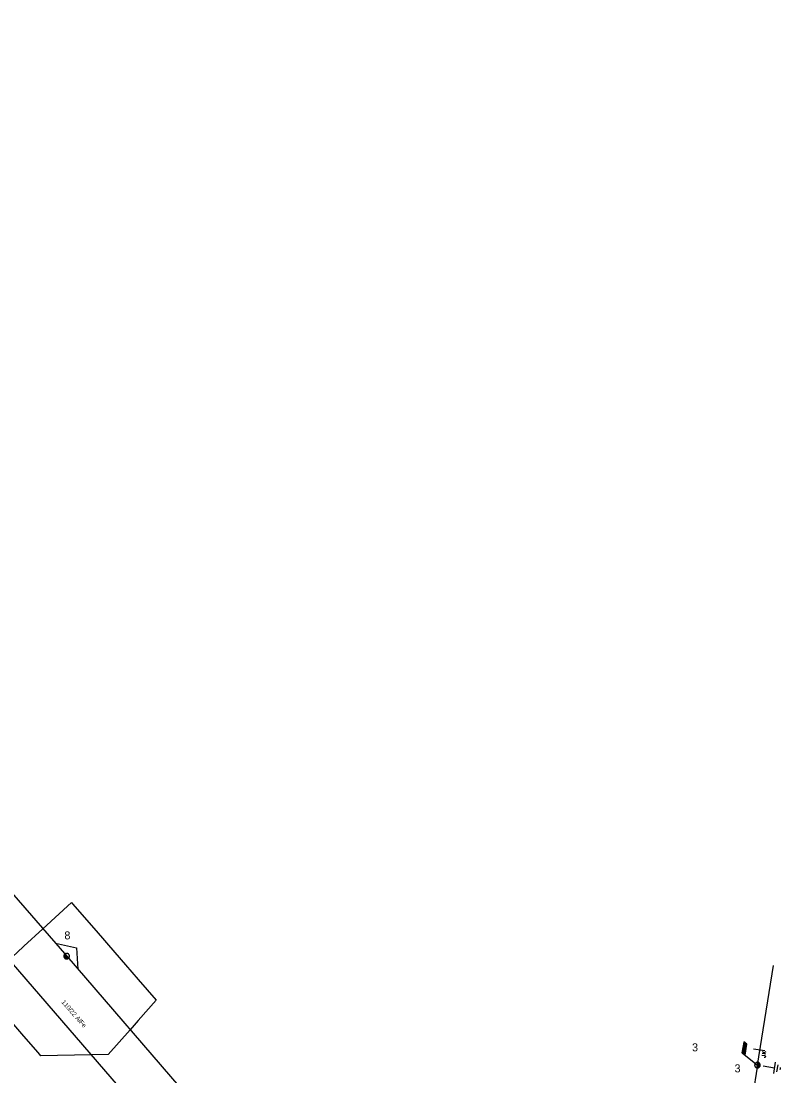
# Model space of a CAD drawing. Extents: x -540879 to -537255, y -1184046 to -1180016.
# Drawn here: x -537563.1 to -537397, y -1180339.5 to -1180108.9 of the extents above; entities that cross this region are included whole.
import ezdxf

# ---------------------------------------------------------------- set-up
doc = ezdxf.new("R2010")
doc.units = 0
for name, color, linetype in [('Default', 7, 'Continuous'), ('Vrstva 1', 7, 'Continuous'), ('Vrstva 11', 7, 'Continuous'), ('Vrstva 12', 7, 'Continuous'), ('Vrstva 13', 7, 'Continuous'), ('Vrstva 14', 7, 'Continuous'), ('Vrstva 15', 7, 'Continuous'), ('Vrstva 18', 7, 'Continuous'), ('Vrstva 2', 7, 'Continuous'), ('Vrstva 35', 7, 'Continuous')]:
    doc.layers.add(name, color=color, linetype=linetype)

# ---------------------------------------------------------------- blocks, each defined once
blk = doc.blocks.new('VN840')
at = {"layer": 'Vrstva 15'}
for points in [[(-0.01, 1.41), (-0.01, -1.09)], [(-1.51, -1.24), (-1.51, -1.15)], [(-1.48, -1.35), (-1.51, -1.24)], [(-1.33, -1.42), (-1.48, -1.35)], [(-1.27, -1.42), (-1.33, -1.42)], [(-1.13, -1.35), (-1.27, -1.42)], [(-1.09, -1.24), (-1.13, -1.35)], [(-1.09, -0.59), (-1.09, -1.24)], [(-0.68, -0.59), (-0.68, -1.42)], [(-0.68, -1.11), (-0.27, -0.59)], [(-0.54, -0.94), (-0.2, -1.42)]]:
    blk.add_lwpolyline(points, dxfattribs=at)
blk = doc.blocks.new('VN860')
at = {"layer": 'Vrstva 15'}
for points in [[(-3.74, 0), (0.01, 2.82)], [(0.01, 2.82), (3.76, 0)]]:
    blk.add_lwpolyline(points, dxfattribs=at)
blk = doc.blocks.new('VN440')
at = {"layer": 'Vrstva 2'}
for points in [[(1.22, 0), (1.21, 0.13), (1.19, 0.25), (1.16, 0.38), (1.11, 0.5), (1.05, 0.61), (0.98, 0.72), (0.9, 0.82), (0.81, 0.91), (0.71, 0.99), (0.6, 1.06), (0.49, 1.12), (0.37, 1.16), (0.25, 1.2), (0.12, 1.22), (-0.01, 1.22), (-0.14, 1.22), (-0.26, 1.2), (-0.39, 1.16), (-0.51, 1.12), (-0.62, 1.06), (-0.73, 0.99), (-0.83, 0.91), (-0.92, 0.82), (-1, 0.72), (-1.07, 0.61), (-1.13, 0.5), (-1.18, 0.38), (-1.21, 0.25), (-1.23, 0.13), (-1.24, 0), (-1.23, -0.13), (-1.21, -0.26), (-1.18, -0.38), (-1.13, -0.5), (-1.07, -0.62), (-1, -0.73), (-0.92, -0.83), (-0.83, -0.92), (-0.73, -1), (-0.62, -1.07), (-0.51, -1.13), (-0.39, -1.17), (-0.26, -1.2), (-0.14, -1.23), (-0.01, -1.23), (0.12, -1.23), (0.25, -1.2), (0.37, -1.17), (0.49, -1.13), (0.6, -1.07), (0.71, -1), (0.81, -0.92), (0.9, -0.83), (0.98, -0.73), (1.05, -0.62), (1.11, -0.5), (1.16, -0.38), (1.19, -0.26), (1.21, -0.13), (1.22, 0)], [(-1.24, 0), (1.22, 0)], [(-1.18, -0.34), (1.1, -0.34)], [(-1.01, -0.63), (0.97, -0.63)], [(-0.74, -0.92), (0.68, -0.92)]]:
    blk.add_lwpolyline(points, dxfattribs=at)
blk = doc.blocks.new('VN810')
at = {"layer": 'Vrstva 14'}
for points in [[(0, -1.25), (0, -3.75)], [(1.25, -3.75), (-1.25, -3.75)], [(0.77, -4.37), (-0.8, -4.37)], [(0, -5), (-0.25, -5)], [(0.27, -5), (0, -5)]]:
    blk.add_lwpolyline(points, dxfattribs=at)
blk = doc.blocks.new('VN001')
at = {"layer": 'Default'}
for p, q in [((1.73, 3.03), (4.14, 3.03)), ((1.76, 3.08), (4.17, 3.08)), ((1.79, 3.13), (4.2, 3.13)), ((1.82, 3.18), (4.23, 3.18)), ((1.85, 3.23), (4.26, 3.23)), ((1.87, 3.28), (4.29, 3.28)), ((1.9, 3.33), (4.32, 3.33)), ((1.93, 3.38), (4.35, 3.38)), ((1.96, 3.43), (4.37, 3.43)), ((1.99, 3.48), (4.4, 3.48)), ((2.02, 3.53), (4.43, 3.53)), ((2.05, 3.58), (4.46, 3.58)), ((2.07, 3.63), (4.49, 3.63)), ((2.1, 3.68), (4.52, 3.68)), ((2.13, 3.73), (2.54, 3.73))]:
    blk.add_line(p, q, dxfattribs=at)
blk.add_lwpolyline([(2.13, 3.73), (0, 0)], dxfattribs=at)
blk.add_lwpolyline([(4.55, 3.73), (2.13, 3.73), (1.7, 2.98), (4.12, 2.99)], close=True, dxfattribs=at)

msp = doc.modelspace()

# ---------------------------------------------------------------- linework, layer by layer
at = {"layer": 'Vrstva 1'}
for points in [[(-537534.01, -1180350.75), (-537569.87, -1180309.27), (-537631.69, -1180238), (-537723.88, -1180132.14), (-537744.24, -1180108.87)], [(-537716.13, -1180125.67), (-537714.92, -1180127.04), (-537625.68, -1180229.9), (-537553.13, -1180313.31), (-537526.37, -1180344.35)], [(-537402.09, -1180337.13), (-537398.61, -1180315.37)], [(-537402.09, -1180337.13), (-537408.66, -1180378.25), (-537415.36, -1180422.31)]]:
    msp.add_lwpolyline(points, dxfattribs=at)
at = {"layer": 'Vrstva 35'}
msp.add_lwpolyline([(-537551.84, -1180301.84), (-537546.7, -1180307.75), (-537542.6, -1180312.5), (-537540.24, -1180315.24), (-537537.51, -1180318.41), (-537533.57, -1180322.97), (-537537.5, -1180327.4), (-537539.27, -1180329.39), (-537544.04, -1180334.78), (-537547.75, -1180334.86), (-537558.79, -1180335.09), (-537559.39, -1180334.39), (-537562.49, -1180330.8), (-537570.41, -1180321.64), (-537570.98, -1180320.98), (-537571.43, -1180320.46), (-537571.96, -1180319.85), (-537565.7, -1180314.09), (-537563.98, -1180312.5), (-537562.5, -1180311.13), (-537558.35, -1180307.31), (-537552.1, -1180301.55)], close=True, dxfattribs=at)

# ---------------------------------------------------------------- block references
at = {"layer": 'Vrstva 11', "rotation": 80.9209611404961}
msp.add_blockref('VN001', (-537402.09, -1180337.13), dxfattribs=at)
at = {"layer": 'Vrstva 13'}
for p, xscale, yscale, rotation in [((-537553.13, -1180313.31), 0.5, 0.5, -49.39143058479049), ((-537402.09, -1180337.13), 0.49999999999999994, 0.5000000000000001, 80.92175000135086)]:
    msp.add_blockref('VN440', p, dxfattribs=dict(at, xscale=xscale, yscale=yscale, rotation=rotation))
at = {"layer": 'Vrstva 15', "rotation": 80.92287501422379}
msp.add_blockref('VN810', (-537402.09, -1180337.13), dxfattribs=at)
at = {"layer": 'Vrstva 18'}
for name, p, rotation in [('VN860', (-537553.13, -1180313.31), -49.39134165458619), ('VN840', (-537401.55, -1180333.77), 80.92467774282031)]:
    msp.add_blockref(name, p, dxfattribs=dict(at, rotation=rotation))

# ---------------------------------------------------------------- texts
at = {"layer": 'Vrstva 12'}
msp.add_text('3', height=1.75, dxfattribs=at).set_placement((-537416.38, -1180334.12))
at = {"layer": 'Vrstva 14'}
for s, p in [('8', (-537553.62, -1180309.65)), ('3', (-537407.09, -1180338.72))]:
    msp.add_text(s, height=1.75, dxfattribs=at).set_placement(p)
at = {"layer": 'Vrstva 2'}
msp.add_text('110/22 AlFe', height=1, rotation=310.844, dxfattribs=at).set_placement((-537554.34, -1180323.42))

doc.saveas('drawing.dxf')
